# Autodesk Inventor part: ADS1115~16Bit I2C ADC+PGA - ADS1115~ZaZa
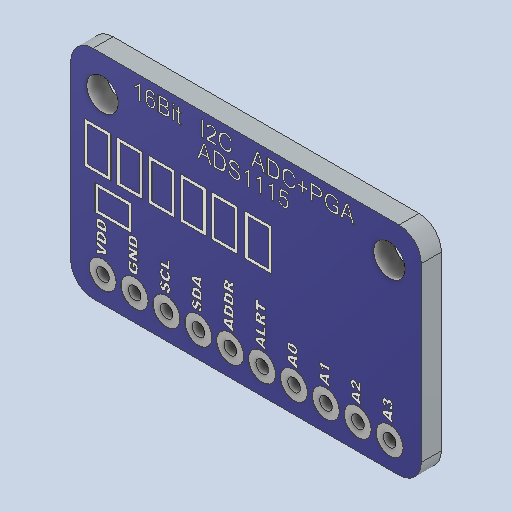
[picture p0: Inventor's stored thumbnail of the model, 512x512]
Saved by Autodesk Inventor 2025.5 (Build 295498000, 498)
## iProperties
Created: 2026-10
Part Number: ADS1115~16Bit I2C ADC+PGA - ADS1115~ZaZa
Material: Genérico
Description: ADS1115
Document SubType Name: Modeling
Designer: Luis M
Density: 1 g/cm^3
Appearance: Valor por defecto
Author: Luis M
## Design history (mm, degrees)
feature "Base1"
node "Sólido1"
